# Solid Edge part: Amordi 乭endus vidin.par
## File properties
Author: KULL
Template: Iso Metric Part.par
Last saved by: KULL
Revision: 11
Application: Solid Edge
Accuracy: 0,990
Face Style: Model Default
Fill Style: Normal
Coef. of Thermal Exp: 0.0
Thermal Conductivity: 0.0
Specific Heat: 0.0
Modulus of Elasticity: 0.0
Poisson's Ratio: 0.0
Yield Stress: 0.0
Ultimate Stress: 0.0
Elongation: 0.0
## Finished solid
Body 1: solid body, 11 faces, 11 edges, 0 vertices.
  Faces by surface: cylinder 4, plane 4, torus 2, blend 1
  Edges by curve: circle 9, intersection 2
Bounding box of the edges (mm; curved faces can reach further): 22.000 x 18.250 x 20.458, from (-11, 40, 41.353) to (11, 58.2501, 61.811).
Cylindrical faces by radius (mm): R2 x1, R2.5 x1, R3 x1, R5 x1
Toroidal faces (ring radius, tube radius in mm): R4.6 r0.4 x2
Planar faces by outward normal: +x 1, -x 1, oblique 2
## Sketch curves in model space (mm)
line (0, 45, 56.811) -> (0, 83.2096, 9.2611)
line (0, 69.3186, 9.2611) -> (0, 92.3796, 9.2611)
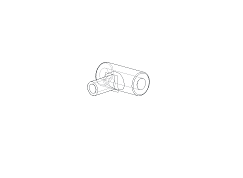
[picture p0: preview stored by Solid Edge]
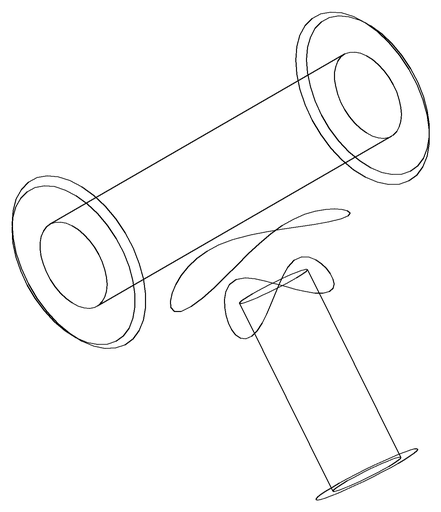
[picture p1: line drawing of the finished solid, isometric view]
